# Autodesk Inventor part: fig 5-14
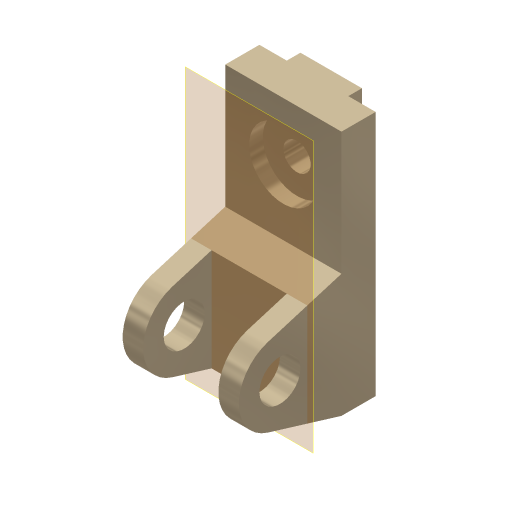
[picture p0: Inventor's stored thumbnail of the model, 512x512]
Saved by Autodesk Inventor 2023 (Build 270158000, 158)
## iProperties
Created: 2001-11
Part Number: fig 5-14
Document SubType Name: Modeling
Designer: Renu Muthoo
Density: 1 g/cm^3
Material: Generic
Appearance: Metal-Titanium (Polished)
Control State: 0
Master: False
Checked Out: False
Shininess: 65.0
Angle Display Precision: 2
Document Length Units: 11269
Document Angle Units: 11279
Document Time Units: 11290
Document Mass Units: 11283
Document Length Units Precision: 3
Document Angle Units Precision: 2
Compacted: False
Density: 0.0
Volumn: 0.0
Area: 0.0
PropertySet Name: Model Information
Author: Renu Muthoo
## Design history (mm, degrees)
node "Sketch1"
sketch "Sketch2"
  geometry: L1 (33.257, 104.664)-(33.257, -75.336); L2 (33.257, -75.336)-(8.257, -75.336); L3 (8.257, -75.336)-(-45.451, -59.045); L4 (-45.451, -1.628)-(8.257, 14.664); L5 (8.257, 14.664)-(8.257, 104.664); L6 (8.257, 104.664)-(33.257, 104.664); C1 r 15 at (-36.743, -30.336); A1 r 30 centre (-36.743, -30.336) between (-45.451, -1.628) and (-45.451, -59.045)
  constraints: 12 end point, 2 centre point, 2 equal length, 2 parallel, 2 point on circle, 2 tangent, 1 coincident, 1 perpendicular, 1 vertical
  dimensions: "d0" = 180 distance of L1.start L1.end; "d1" = 30 radius of A1; "d2" = 25 distance of L5.end L1.start; "d3" = 45 distance from line of L2 A1.centre; "d4" = 70 distance from line of L1 A1.centre; "d5" = 30 diameter of C1
extrude "Extrusion1" new body sketch "Sketch2" distance "d6" = 85; taper "d7" = 0 deg
workplane "Work Plane1"
sketch "Sketch3"
  geometry: L1 (15, 62.364)-(70, 62.364); L2 (70, 62.364)-(70, -52.386); L3 (70, -52.386)-(15, -52.386); L4 (15, -52.386)-(15, 62.364); L5 (0, -45)-(0, -28.708) reference
  constraints: 8 end point, 2 parallel, 1 horizontal, 1 perpendicular
  dimensions: "d8" = 55 distance of L1.start L1.end; "d9" = 15 distance between parallel lines of L5 L4
extrude "Extrusion2" cut sketch "Sketch3" distance "d10" = 50; taper "d11" = 0 deg
sketch "Sketch4"
  geometry: L1 (0, 25)-(85, 25) reference; L2 (0, 0)-(0, 25) reference; L3 (20, 25)-(65, 25); L4 (65, 25)-(65, 35); L5 (65, 35)-(20, 35); L6 (20, 35)-(20, 25)
  constraints: 8 end point, 2 parallel, 1 horizontal, 1 perpendicular, 1 point on line
  dimensions: "d12" = 45 distance of L4.end L5.end; "d13" = 10 distance of L3.end L4.end; "d14" = 20 distance between parallel lines of L2 L6
extrude "Extrusion3" join sketch "Sketch4" stored distance "d15" = 50; taper "d16" = 0 deg
sketch "Sketch5"
  geometry: L1 (85, 0)-(85, 90) reference; L2 (0, 90)-(85, 90) reference; 1 further point
  dimensions: "d17" = 42 distance from line of L2 point (42.5, 48); "d18" = 42.5 distance from line of L1 point (42.5, 48)
hole "Hole1" sketch "Sketch5" at (42.5, 48) diameter "d19" = 20; stored, may be unused: countersink angle "d23" = 82 deg, drill point angle "d25" = 118 deg; dims "d20" = 6, "d21" = 50, "d22" = 10, "d24" = 8
workplane "Work Plane6"
body "Solid1"
other parameters: "d26" = 0
